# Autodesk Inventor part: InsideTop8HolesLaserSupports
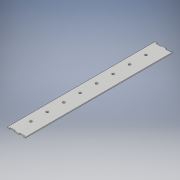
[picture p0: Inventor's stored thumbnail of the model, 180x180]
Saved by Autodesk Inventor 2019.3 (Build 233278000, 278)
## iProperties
Created: 2020-02
Part Number: InsideTop8HolesLaserSupports
Material: Generic
Document SubType Name: Modeling
Designer: KrystynWikoff
Density: 1 g/cm^3
Appearance: Default
Author: KrystynWikoff
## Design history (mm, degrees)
sketch "Sketch1"
  geometry: L1 (0, 0)-(101.6, 0); L2 (101.6, 0)-(101.6, -398.424); L3 (101.6, -398.424)-(0, -398.424); L4 (0, -398.424)-(0, 0)
  constraints: 8 end point, 2 parallel, 1 horizontal, 1 perpendicular
  dimensions: "d0" = 398.4244 distance of L3.end L1.start; "d1" = 101.6 distance of L1.start L1.end
extrude "Extrusion1" new body sketch "Sketch1" distance "d2" = 2.3622; taper "d3" = 0 deg
sketch "Sketch3" dims "d30" = 25.4, "d41" = 25.4
  geometry: L1 (0, 0)-(-101.6, 0) reference; L2 (-76.2, 0)-(-88.9, 0); L3 (-88.9, 0)-(-88.9, 2.362); L4 (-88.9, 2.362)-(-76.2, 2.362); L5 (-76.2, 2.362)-(-76.2, 0); L6 (-101.6, 398.424)-(-101.6, 0) reference; L7 (-50.8, 0)-(-63.5, 0); L8 (-63.5, 0)-(-63.5, 2.362); L9 (-63.5, 2.362)-(-50.8, 2.362); L10 (-50.8, 2.362)-(-50.8, 0); L11 (-25.4, 0)-(-38.1, 0); L12 (-38.1, 0)-(-38.1, 2.362); L13 (-38.1, 2.362)-(-25.4, 2.362); L14 (-25.4, 2.362)-(-25.4, 0); L15 (0, 0)-(-12.7, 0); L16 (-12.7, 0)-(-12.7, 2.362); L17 (-12.7, 2.362)-(0, 2.362); L18 (0, 2.362)-(0, 0); L19 (-88.9, 398.424)-(-76.2, 398.424); L20 (-76.2, 398.424)-(-76.2, 396.062); L21 (-76.2, 396.062)-(-88.9, 396.062); L22 (-88.9, 396.062)-(-88.9, 398.424); L23 (0, 398.424)-(-101.6, 398.424) reference; L24 (-101.6, 398.424)-(-101.6, 0) reference; L25 (-50.8, 398.424)-(-50.8, 396.062); L26 (-50.8, 396.062)-(-63.5, 396.062); L27 (-63.5, 396.062)-(-63.5, 398.424); L28 (-63.5, 398.424)-(-50.8, 398.424); L29 (-25.4, 398.424)-(-25.4, 396.062); L30 (-25.4, 396.062)-(-38.1, 396.062); L31 (-38.1, 396.062)-(-38.1, 398.424); L32 (-38.1, 398.424)-(-25.4, 398.424); L33 (0, 398.424)-(0, 396.062); L34 (0, 396.062)-(-12.7, 396.062); L35 (-12.7, 396.062)-(-12.7, 398.424); L36 (-12.7, 398.424)-(0, 398.424); 6 further points
  constraints: 64 end point, 4 horizontal, 4 parallel, 2 perpendicular, 1 point on line, 48 other
  dimensions: "d22" = 2.3622 distance of L4.end L2.start; "d23" = 12.7 distance between parallel lines of L6 L3; "d24" = 12.7 distance of L3.end L4.end; "d27" = 25.4 distance of L2.start L7.start; "d32" = 2.3622 distance of L19.end L20.end; "d33" = 0 distance between parallel lines of L23 L19; "d34" = 12.7 distance between parallel lines of L24 L22; "d35" = 12.7 distance of L20.end L21.end; "d38" = 25.4 distance of L20.end L25.end
extrude "Extrusion3" cut sketch "Sketch3" distance "d43" = 2.3622; taper "d44" = 0 deg
sketch "Sketch4" dims "d53" = 25.4
  geometry: L1 (-101.6, 398.424)-(-101.6, 0) reference; L2 (-50.8, 0)-(-38.1, 0) reference; C1 r 3.01 at (-50.8, 44.45); C2 r 3.01 at (-50.8, 88.9); C3 r 3.01 at (-50.8, 133.35); C4 r 3.01 at (-50.8, 177.8); C5 r 3.01 at (-50.8, 222.25); C6 r 3.01 at (-50.8, 266.7); C7 r 3.01 at (-50.8, 311.15); C8 r 3.01 at (-50.8, 355.6); 3 further points
  constraints: 8 centre point, 1 vertical, 14 other
  dimensions: "d45" = 6.0198 diameter of C1; "d46" = 50.8 distance from line of C1.centre L1; "d47" = 44.45 distance from line of L2 C1.centre; "d50" = 44.45 distance of C1.centre C2.centre
extrude "Extrusion4" cut sketch "Sketch4" distance "d55" = 25.4; taper "d56" = 0 deg
sketch "Sketch6"
  geometry: L1 (-63.5, 0)-(-76.2, 0) reference; L2 (-69.85, 0)-(-21.59, 0); L3 (-21.59, 0)-(-21.59, 398.462); L4 (-21.59, 398.462)-(-69.85, 398.462); L5 (-69.85, 398.462)-(-69.85, 0); L6 (-21.59, 0)-(0, 0); L7 (0, 0)-(0, 398.462); L8 (0, 398.462)-(-21.59, 398.462); L9 (-21.59, 398.462)-(-21.59, 0); L10 (-101.6, 398.424)-(-101.6, 0) reference; L11 (-69.85, 398.462)-(-101.6, 398.462); L12 (-101.6, 398.462)-(-101.6, 0); L13 (-101.6, 0)-(-69.85, 0); L14 (-69.85, 0)-(-69.85, 398.462); 1 further point
  constraints: 24 end point, 6 parallel, 3 horizontal, 3 perpendicular, 1 midpoint
  dimensions: "d74" = 48.26 distance of L2.start L2.end; "d75" = 398.4625 distance of L4.end L2.start; "d76" = 398.4625 distance of L6.end L7.end; "d77" = 21.59 distance of L7.end L8.end
extrude "Extrusion6" cut sketch "Sketch6" extent not by distance; stored distance "d78" = 0; taper "d79" = 0 deg
body "Solid1"
